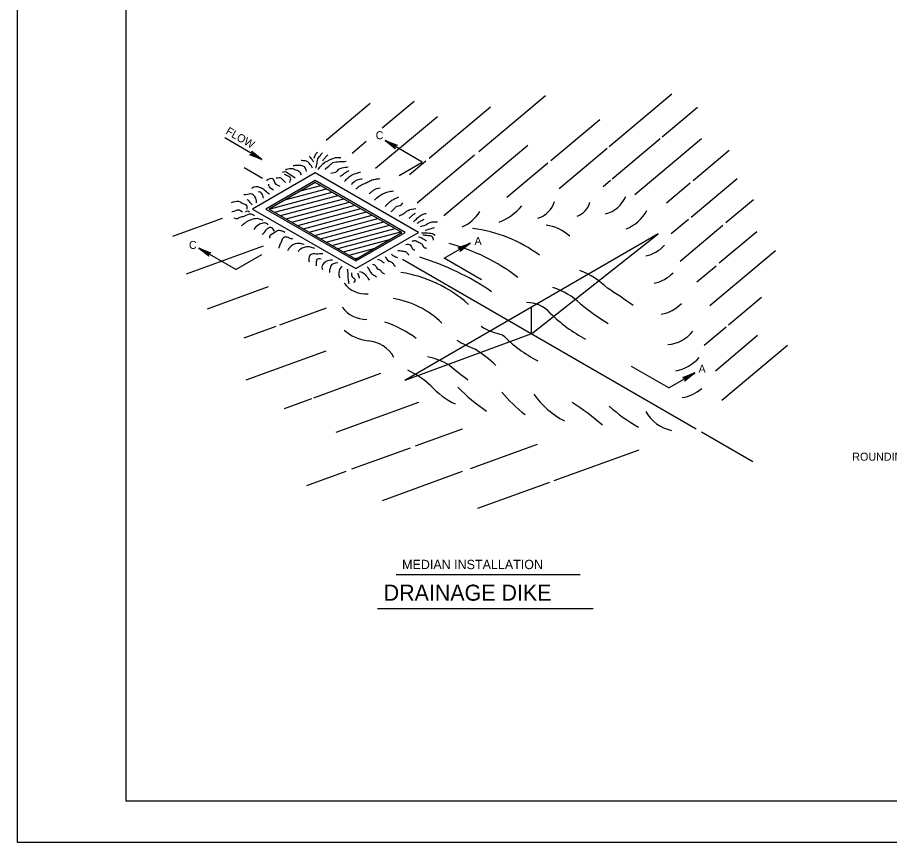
# Model space of a CAD drawing. Extents: x 69 to 973, y -48 to 546.
# Drawn here: x 68.6 to 382.3, y -48 to 249 of the extents above; entities that cross this region are included whole.
import ezdxf

# ---------------------------------------------------------------- set-up
doc = ezdxf.new("R2010")
doc.units = 0
for name, color, linetype in [('1', 7, 'Continuous'), ('2', 7, 'Continuous'), ('3', 7, 'Continuous'), ('PLT-BNDY', 7, 'Continuous')]:
    doc.layers.add(name, color=color, linetype=linetype)

msp = doc.modelspace()

# ---------------------------------------------------------------- linework, layer by layer
at = {"layer": '1'}
msp.add_lwpolyline([(893.57, -33.04), (893.57, 530.96), (107.57, 530.96), (107.57, -33.04), (893.57, -33.04), (893.57, -6.68), (693.57, -6.68), (693.57, 58), (893.57, 58), (893.57, 86.96), (693.57, 86.96), (693.57, -33.04), (772.37, -33.04), (772.37, -6.68), (772.37, -33.04), (849.37, -33.04), (849.37, -6.68), (849.37, -19), (893.57, -19)], dxfattribs=at)
at = {"layer": '2'}
for p, q in [((234.52, 200.75), (258.5, 220.87)), ((281.49, 202.56), (304, 221.46)), ((179.65, 204.84), (195.44, 218.09)), ((199.77, 209.18), (211.29, 218.85)), ((216.72, 198.35), (238.71, 216.8)), ((300.54, 206.02), (313.25, 216.69)), ((197.44, 194.7), (219.68, 213.36)), ((260.51, 197.49), (278.12, 212.27)), ((156.54, 197.88), (143.16, 205.61)), ((189.01, 200.16), (194.06, 204.4)), ((214.23, 196.9), (200.84, 204.63)), ((282.53, 190.9), (299.75, 205.36)), ((290.69, 185.22), (314.66, 205.34)), ((221.95, 177.67), (252.13, 203)), ((263.42, 187.41), (280.68, 201.89)), ((311.7, 190.32), (324.58, 201.13)), ((212.41, 182.2), (233.04, 199.51)), ((156.75, 190.96), (150.15, 194.77)), ((205.85, 192.06), (214.23, 196.9)), ((209.67, 192.43), (215.51, 197.33)), ((244.67, 184.21), (259.42, 196.58)), ((170.34, 186.49), (177.7, 188.46)), ((279.26, 188.16), (281.94, 190.41)), ((302.08, 182.25), (310.63, 189.42)), ((310.91, 177.12), (327.47, 191.02)), ((159.1, 180), (181.81, 186.09)), ((164.72, 183.25), (179.75, 187.27)), ((161.16, 178.81), (183.87, 184.9)), ((163.21, 177.62), (185.93, 183.71)), ((165.27, 176.44), (187.98, 182.52)), ((323.46, 175.12), (333.42, 183.48)), ((167.33, 175.25), (190.04, 181.33)), ((169.39, 174.06), (192.1, 180.15)), ((171.44, 172.87), (194.16, 178.96)), ((124.51, 170.26), (142.33, 176.75)), ((173.5, 171.68), (196.21, 177.77)), ((175.56, 170.5), (198.27, 176.58)), ((303.77, 171.13), (310.01, 176.37)), ((177.62, 169.31), (200.33, 175.39)), ((179.67, 168.12), (202.39, 174.21)), ((181.73, 166.93), (204.44, 173.02)), ((306.93, 161.25), (322.39, 174.22)), ((183.79, 165.75), (206.5, 171.83)), ((299.08, 171.11), (207.88, 118.31)), ((253.48, 135.11), (299.08, 171.11)), ((321.07, 160.59), (334.53, 171.88)), ((129.44, 156.73), (157.14, 166.81)), ((185.85, 164.56), (202.37, 168.99)), ((222.12, 162.26), (231.47, 167.66)), ((147.18, 158.19), (133.8, 165.92)), ((147.18, 158.19), (156.53, 163.59)), ((187.9, 163.37), (196.75, 165.74)), ((317.69, 145.22), (341.34, 165.06)), ((189.96, 162.18), (191.13, 162.49)), ((207.06, 161.91), (312.73, 100.9)), ((235.5, 154.53), (222.12, 162.26)), ((312.95, 153.78), (319.9, 159.6)), ((136.92, 144.13), (158.92, 152.14)), ((324.33, 138.26), (336.25, 148.26)), ((162.95, 138.28), (179.81, 144.41)), ((253.48, 135.11), (253.48, 144.71)), ((150.19, 133.63), (161.62, 137.8)), ((253.48, 135.11), (207.88, 118.31)), ((253.48, 135.11), (253.48, 135.11)), ((253.55, 135.07), (253.55, 135.07)), ((315.61, 130.94), (323.55, 137.6)), ((319.65, 121.79), (334.85, 134.55)), ((150.81, 118.54), (179.6, 129.01)), ((321.99, 111.23), (345.55, 131)), ((302.92, 115.61), (289.53, 123.34)), ((175.14, 112.07), (199.36, 120.88)), ((302.92, 115.61), (312.27, 121.01)), ((164.59, 108.23), (174.47, 111.82)), ((183.27, 99.7), (212.92, 110.49)), ((211.78, 94.75), (228.72, 100.92)), ((314.68, 99.78), (333.15, 89.11)), ((231.58, 86.64), (255.72, 95.42)), ((188.91, 86.43), (209.97, 94.09)), ((261.67, 82.26), (292.22, 93.38)), ((172.63, 80.51), (186.85, 85.68)), ((199.89, 75.1), (228.74, 85.6)), ((234.23, 72.28), (260.1, 81.69))]:
    msp.add_line(p, q, dxfattribs=at)
for points in [[(204.34, 201.98), (204.36, 202.33), (200.84, 204.63), (204.34, 201.98), (204.44, 201.7), (200.84, 204.63), (204.58, 202.71), (204.86, 202.91), (200.84, 204.63), (205.17, 202.97), (204.86, 202.91)], [(153.04, 200.53), (153.02, 200.18), (156.54, 197.88), (153.04, 200.53), (152.94, 200.81), (156.54, 197.88), (152.81, 199.79), (152.52, 199.6), (156.54, 197.88), (152.21, 199.54), (152.52, 199.6)], [(175.73, 193.06), (153.1, 180), (190.27, 158.54), (212.9, 171.6), (175.73, 193.06)], [(175.73, 190.29), (157.9, 180), (190.27, 161.31), (208.1, 171.6), (175.73, 190.29)], [(175.73, 189.6), (175.73, 189.6), (159.1, 180), (190.27, 162), (206.9, 171.6), (175.73, 189.6)], [(227.42, 165.95), (227.72, 165.76), (231.47, 167.66), (227.42, 165.95), (227.13, 166.01), (231.47, 167.66), (227.94, 165.38), (227.97, 165.03), (231.47, 167.66), (227.86, 164.74), (227.97, 165.03)], [(137.3, 163.27), (137.31, 163.62), (133.8, 165.92), (137.3, 163.27), (137.39, 162.99), (133.8, 165.92), (137.53, 164), (137.82, 164.2), (133.8, 165.92), (138.13, 164.26), (137.82, 164.2)], [(308.22, 119.3), (308.52, 119.11), (312.27, 121.01), (308.22, 119.3), (307.93, 119.36), (312.27, 121.01), (308.74, 118.73), (308.76, 118.38), (312.27, 121.01), (308.66, 118.09), (308.76, 118.38)]]:
    msp.add_lwpolyline(points, dxfattribs=at)
for centre, radius, start, end in [((253.18, 185.33), 9.02, 286.5276, 343.4724), ((267.69, 184.04), 6.97, 288.7333, 347.2935), ((277.24, 188.84), 11.03, 285.4619, 337.049), ((223.65, 185.72), 13.02, 291.9877, 329.4067), ((234.23, 194.74), 20.88, 291.3154, 319.2625), ((282.43, 186.21), 14.26, 290.9609, 331.8248), ((225.88, 122.03), 51.38, 53.5938, 82.8044), ((256.66, 158.44), 15.86, 48.0298, 82.3127), ((205.82, 99.81), 70.11, 52.4697, 75.1094), ((292.03, 175.54), 12.67, 281.7883, 317.2326), ((185.45, 71.51), 95.29, 55.6923, 72.9896), ((199.28, 110.56), 47.18, 48.0738, 81.2095), ((260.59, 130.71), 29.02, 45.8075, 69.1048), ((294.27, 167.41), 14.55, 283.4646, 314.6419), ((193.85, 159.18), 9.75, 217.3527, 275.0369), ((252.39, 125.18), 27.98, 47.8565, 71.6635), ((146.26, -58), 249.01, 54.7246, 57.2897), ((198.3, 115.19), 33.07, 45.9376, 80.6071), ((194.39, 151.66), 11.44, 217.7782, 269.088), ((251.98, 135.37), 10.93, 41.0955, 91.5243), ((317.1, 199.55), 70.61, 229.4134, 239.3198), ((297.96, 154.82), 12.9, 279.9706, 317.1109), ((299.45, 182.26), 55.81, 225.3474, 241.6775), ((188.36, 102.15), 39.2, 52.8051, 71.5152), ((196.68, 148.44), 16.02, 228.6309, 262.8844), ((247.47, 157.26), 22.92, 238.0896, 258.9586), ((301.75, 143.53), 12.33, 273.9458, 322.5888), ((193.99, 121.16), 11.41, 28.5376, 86.425), ((253.97, 180.31), 54.87, 240.108, 247.7863), ((278.12, 168.87), 48.89, 224.2266, 242.77), ((211.09, 93.85), 41.98, 45.1865, 58.1828), ((210.91, 100.95), 26.37, 60.1553, 78.6166), ((302.15, 137.41), 15.99, 281.2273, 317.1701), ((285.04, 192.85), 92.13, 228.5297, 233.7377), ((193.72, 90.52), 34.99, 47.7356, 64.0678), ((238.59, 135.63), 28.72, 222.0195, 243.9818), ((276.2, 164.09), 68.86, 224.4053, 235.5658), ((280.33, 144.43), 48.21, 218.9436, 232.8137), ((279.31, 130.82), 30.45, 214.964, 242.7567), ((305.08, 126.96), 15.08, 279.8813, 309.9227), ((219.13, 33.09), 91.49, 49.0893, 57.5988), ((326.29, 160.02), 67.88, 228.6558, 239.6195), ((306.5, 113.56), 13.49, 208.2851, 258.7324)]:
    msp.add_arc(centre, radius, start, end, dxfattribs=at)
for points in [[(175.15, 197), (173.98, 198.54), (173.61, 198.97)], [(175.34, 198.29), (175.77, 199.59), (176.58, 200.52)], [(175.94, 194.72), (176.35, 196.47), (176.48, 197.56), (177.56, 199.31), (178.37, 200.4)], [(176.58, 194.22), (177.63, 195.33), (178.43, 196.25), (181.71, 198.05), (182.45, 198.36), (184.86, 198.6)], [(178.31, 197.37), (179.11, 198.29), (179.79, 199.04), (180.28, 199.47)], [(170.77, 192.36), (169.84, 193.54), (168.42, 194.15), (168.29, 194.22), (166.93, 194.52), (164.83, 194.03)], [(172.56, 193.54), (172, 195.02), (171.01, 195.51), (169.34, 195.7), (167.74, 195.51)], [(174.72, 194.65), (173.55, 196.5), (172.5, 197.24), (170.83, 197.43), (170.58, 197.49)], [(179.23, 194.28), (181.03, 195.88), (182.08, 196.69), (184.49, 197.06), (186.77, 197.18)], [(181.33, 192.92), (183.5, 193.6), (184.05, 194.22), (185.35, 194.83), (187.58, 195.14)], [(168.48, 191.06), (166.38, 192.55), (164.77, 193.35), (163.78, 193.16)], [(166.56, 189.58), (166.81, 191.19), (165.33, 192.11), (164.65, 192.42)], [(184.73, 191.8), (186.22, 192.86), (187.76, 193.91)], [(186.28, 189.95), (187.51, 191.25), (188.69, 192.18), (190.91, 192.98), (191.96, 193.29)], [(163.1, 188.16), (161.37, 189.21), (160.69, 190.57), (160.44, 190.82), (158.16, 190.2)], [(160.69, 186.8), (159.02, 188.47), (158.96, 188.9)], [(165.02, 189.58), (163.97, 190.57), (163.1, 191.25), (162.24, 191.13), (161.68, 191.06)], [(188.69, 188.84), (189.8, 189.89), (190.73, 190.51), (192.58, 190.88)], [(190.36, 187.17), (191.16, 187.91), (192.77, 188.9), (194.25, 189.58), (195.73, 190.32), (197.34, 190.75), (198.89, 190.94)], [(154.63, 182.22), (154.02, 184.45), (152.59, 185.44), (150.18, 185.13), (150, 185.19)], [(159.21, 185.32), (157.17, 186.98), (155.81, 187.79), (152.97, 187.48), (152.9, 187.42)], [(157.04, 183.89), (156.36, 185.69), (155.87, 186.06), (155.13, 186.12)], [(195.12, 185.5), (195.98, 186.24), (196.79, 186.86), (199.01, 187.66)], [(196.97, 183.15), (198.83, 184.76), (200.18, 185.56), (201.98, 186.24), (203.83, 186.49)], [(151.23, 180), (150.86, 181.48), (149.38, 182.04), (148.76, 182.47), (146.17, 182.47), (145.43, 182.22)], [(152.97, 181.48), (152.47, 182.1), (151.54, 183.15), (151.23, 183.34)], [(200.86, 180.93), (201.73, 181.79), (202.66, 182.72), (203.95, 183.52), (205.81, 184.33)], [(202.97, 179.07), (204.02, 179.94), (204.7, 180.74), (206.67, 181.55), (207.17, 182.22)], [(149.5, 178.83), (148.08, 179.63), (145.8, 178.95), (145.67, 178.95)], [(150.62, 178.89), (151.36, 179.32), (151.91, 178.89)], [(205.93, 177.59), (207.35, 178.27), (208.03, 178.76), (209.08, 179.51), (211.93, 180.19)], [(153.83, 177.59), (152.66, 178.15), (150.06, 177.34), (148.58, 176.91), (147.28, 176.48), (146.48, 176.66)], [(156.8, 175.86), (155.31, 176.48), (153.21, 176.29), (151.23, 175.49), (150.43, 174.93), (149.2, 174)], [(209.46, 176.72), (210.32, 177.4), (210.82, 177.9), (211.8, 178.45)], [(211.06, 175.36), (212.42, 176.72), (213.47, 177.59), (214.89, 178.27), (215.64, 178.39)], [(212.42, 174.81), (213.41, 175.55), (214.03, 175.86), (214.71, 176.29)], [(158.78, 174.31), (157.48, 174.99), (157.29, 174.99), (155.68, 174.5), (153.89, 172.95), (153.58, 172.46)], [(161, 171.97), (160.07, 173.26), (158.53, 172.95), (157.29, 171.47), (156.61, 170.73)], [(213.6, 173.76), (216.01, 174.62), (217, 175.18), (218.48, 175.36), (219.65, 175.36)], [(215.2, 172.34), (217.74, 173.08), (218.66, 173.39)], [(164.77, 171.53), (163.91, 171.97), (162.48, 172.21), (160.81, 171.35), (159.27, 169.8), (159.39, 169.68)], [(167.68, 169.12), (166.32, 169.55), (164.89, 169.93), (163.84, 169.18), (163.29, 167.76), (162.67, 166.4), (162.55, 165.91)], [(212.86, 169.99), (214.52, 169.31), (215.39, 168.75), (215.7, 168.63)], [(213.91, 171.47), (216.81, 171.35), (217.3, 171.29), (218.11, 171.04), (218.73, 170.48)], [(214.4, 170.73), (215.82, 170.54), (217.74, 170.11), (218.17, 168.75)], [(171.69, 167.21), (169.22, 167.64), (166.44, 166.03), (165.7, 164.92)], [(175.52, 165.78), (173.98, 166.28), (173.18, 166.4), (170.39, 165.54), (169.84, 165.1), (169.59, 164.55)], [(208.28, 167.27), (209.83, 167.08), (210.32, 166.34), (210.94, 165.48), (211.5, 165.29)], [(210.57, 168.44), (211.68, 168.63), (213.1, 167.95), (214.21, 167.21), (214.65, 166.34), (215.7, 165.91)], [(178.43, 163.93), (176.08, 163.81), (174.04, 163.56), (173.42, 162.39), (173.49, 160.96)], [(203.03, 163.81), (203.83, 163.19), (204.63, 162.82), (205.31, 162.57)], [(205.38, 165.1), (206.55, 164.98), (207.79, 164.73), (208.41, 164.55), (209.21, 163.62), (209.46, 163.44)], [(177.81, 162.01), (176.27, 161.83), (176.08, 160.65), (176.02, 159.54)], [(181.95, 161.64), (179.54, 161.09), (179.23, 160.9), (178.12, 159.05), (178.37, 158.18)], [(183.87, 160.59), (181.27, 159.54), (181.09, 158.74), (180.84, 157.44), (180.96, 157.13)], [(196.29, 160.16), (197.22, 159.73), (198.39, 158.31), (199.13, 158), (199.44, 157.5), (200.56, 156.7)], [(198.15, 161.95), (199.38, 161.46), (200.06, 160.9), (200.49, 160.65)], [(200.86, 162.88), (202.16, 161.27), (203.15, 160.9), (203.83, 160.1), (204.2, 159.54), (204.63, 159.36)], [(185.41, 159.42), (184.3, 157.75), (184.24, 157.32), (184.3, 155.71), (184.61, 155.28)], [(187.21, 158.43), (187.39, 157.26), (187.39, 155.71), (187.51, 154.6), (187.76, 153.24)], [(188.69, 157.01), (189.06, 155.46), (189.93, 154.72), (189.55, 153.42)], [(190.85, 157.07), (191.41, 155.71), (191.47, 155.09)], [(191.66, 157.56), (193.32, 156.76), (194.68, 155.09), (195.12, 154.35)], [(194.44, 159.23), (195.12, 158.06), (195.92, 156.82), (197.09, 156.02), (197.71, 155.59)]]:
    msp.add_spline(points, degree=3, dxfattribs=at)
at = {"layer": '3'}
for p, q in [((204.82, 48.45), (270.97, 48.45)), ((198.11, 36.24), (275.65, 36.24))]:
    msp.add_line(p, q, dxfattribs=at)
at = {"layer": 'PLT-BNDY'}
msp.add_lwpolyline([(68.57, 545.96), (909.57, 545.96), (909.57, -48.04), (68.57, -48.04)], close=True, dxfattribs=at)

# ---------------------------------------------------------------- texts
at = {"layer": '3'}
msp.add_text('FLOW', height=2.88, rotation=329.9986, dxfattribs=at).set_placement((143.23, 207.22))
for s, height, p in [('C', 2.88, (197.43, 205.12)), ('A', 2.88, (233, 167.07)), ('C', 2.88, (130.27, 165.64)), ('A', 2.88, (313.59, 121.07)), ('ROUNDING REQUIRED', 2.88, (368.91, 89.41)), ('MEDIAN INSTALLATION', 3.36, (206.96, 50.38)), ('DRAINAGE DIKE', 5.76, (200.33, 39.03))]:
    msp.add_text(s, height=height, dxfattribs=at).set_placement(p)

doc.saveas('drawing.dxf')
